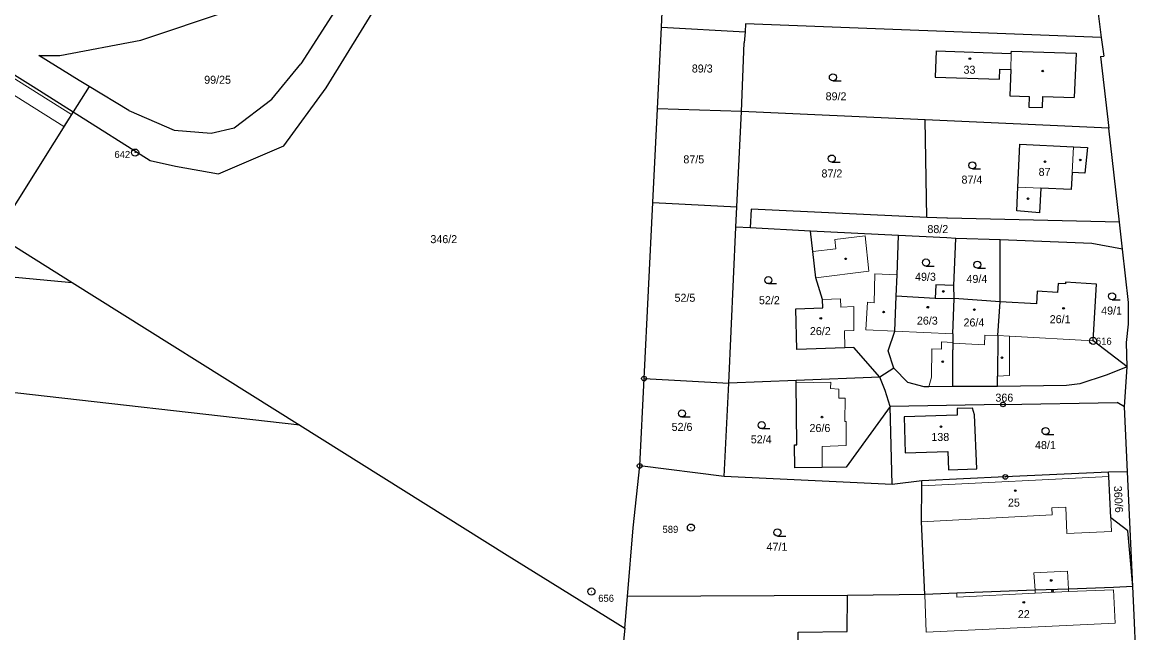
# Model space of a CAD drawing. Extents: x -645290 to -643454, y -1064771 to -1062356.
# Drawn here: x -644815.8 to -644579.3, y -1063657.6 to -1063528 of the extents above; entities that cross this region are included whole.
import ezdxf
from ezdxf.enums import TextEntityAlignment as Align

# ---------------------------------------------------------------- set-up
doc = ezdxf.new("R2010")
doc.units = 0
doc.header["$LTSCALE"] = 0.68
for name, color, linetype, lineweight in [('1', 7, 'Continuous', 25), ('13', 7, 'Continuous', 13), ('3', 7, 'Continuous', 25), ('4', 7, 'Continuous', 13), ('5', 7, 'Continuous', 25), ('8', 7, 'Continuous', 25)]:
    doc.layers.add(name, color=color, linetype=linetype, lineweight=lineweight)
doc.layers.add('2', color=7, linetype='Continuous')

msp = doc.modelspace()

# ---------------------------------------------------------------- linework, layer by layer
at = {"layer": '1'}
for p, q in [((-644680.03, -1063529.01), (-644678.93, -1063506.84)), ((-644589.39, -1063509.99), (-644586.6, -1063531.21)), ((-644743.97, -1063517.12), (-644756.66, -1063536.79)), ((-644751.27, -1063541.95), (-644735.12, -1063515.68)), ((-644790.62, -1063531.79), (-644771.77, -1063525.53)), ((-644680.89, -1063546.4), (-644680.03, -1063529.01)), ((-644680.03, -1063529.01), (-644662.28, -1063530.06)), ((-644662.16, -1063528.35), (-644662.28, -1063530.06)), ((-644586.6, -1063531.21), (-644662.16, -1063528.35)), ((-644662.28, -1063530.06), (-644662.43, -1063532.35)), ((-644586.6, -1063531.21), (-644586.08, -1063535.17)), ((-644807.8, -1063535.04), (-644790.62, -1063531.79)), ((-644663.05, -1063546.91), (-644662.43, -1063532.35)), ((-644824.28, -1063534.96), (-644813.5, -1063541.61)), ((-644803.7, -1063540.34), (-644812.29, -1063535.02)), ((-644812.29, -1063535.02), (-644807.8, -1063535.04)), ((-644621.67, -1063534.04), (-644621.87, -1063539.63)), ((-644621.67, -1063534.04), (-644605.72, -1063534.61)), ((-644605.72, -1063534.61), (-644605.71, -1063534.15)), ((-644605.71, -1063534.15), (-644591.95, -1063534.59)), ((-644591.95, -1063534.59), (-644592.37, -1063543.94)), ((-644586.76, -1063535.29), (-644586.08, -1063535.17)), ((-644586.76, -1063535.29), (-644585, -1063550.46)), ((-644762.81, -1063544.34), (-644756.66, -1063536.79)), ((-644608.24, -1063540.05), (-644608.17, -1063537.95)), ((-644608.17, -1063537.95), (-644605.83, -1063538.02)), ((-644605.83, -1063538.02), (-644606.01, -1063543.63)), ((-644801.59, -1063541.62), (-644803.7, -1063540.34)), ((-644621.87, -1063539.63), (-644608.24, -1063540.05)), ((-644813.5, -1063541.61), (-644804.99, -1063547)), ((-644801.59, -1063541.62), (-644804.99, -1063547)), ((-644793.15, -1063546.73), (-644801.59, -1063541.62)), ((-644760.23, -1063554.23), (-644751.27, -1063541.95)), ((-644770.83, -1063550.4), (-644762.81, -1063544.34)), ((-644606.01, -1063543.63), (-644601.9, -1063543.75)), ((-644601.9, -1063543.75), (-644601.97, -1063545.99)), ((-644599.09, -1063546.08), (-644599.02, -1063543.73)), ((-644599.02, -1063543.73), (-644592.37, -1063543.94)), ((-644804.99, -1063547), (-644820.87, -1063572.2)), ((-644804.99, -1063547), (-644788.64, -1063557.36)), ((-644793.15, -1063546.73), (-644783.51, -1063550.89)), ((-644681.88, -1063566.23), (-644680.89, -1063546.4)), ((-644663.05, -1063546.91), (-644680.89, -1063546.4)), ((-644664.01, -1063567.2), (-644663.05, -1063546.91)), ((-644624, -1063548.69), (-644663.05, -1063546.91)), ((-644601.97, -1063545.99), (-644599.09, -1063546.08)), ((-644775.65, -1063551.57), (-644770.83, -1063550.4)), ((-644585, -1063550.46), (-644624, -1063548.69)), ((-644623.68, -1063569.41), (-644624, -1063548.69)), ((-644582.74, -1063570.45), (-644585, -1063550.46)), ((-644783.51, -1063550.89), (-644775.65, -1063551.57)), ((-644774.12, -1063560.19), (-644760.23, -1063554.23)), ((-644604.32, -1063562.98), (-644603.9, -1063553.89)), ((-644603.9, -1063553.89), (-644592.51, -1063554.41)), ((-644592.51, -1063554.41), (-644589.57, -1063554.58)), ((-644589.57, -1063554.58), (-644590.07, -1063560.04)), ((-644788.64, -1063557.36), (-644783.26, -1063558.56)), ((-644783.26, -1063558.56), (-644774.12, -1063560.19)), ((-644592.81, -1063559.88), (-644593.01, -1063563.53)), ((-644590.07, -1063560.04), (-644592.81, -1063559.88)), ((-644604.57, -1063568.05), (-644604.32, -1063562.98)), ((-644599.45, -1063563.22), (-644599.71, -1063568.44)), ((-644593.01, -1063563.53), (-644599.45, -1063563.22)), ((-644683.74, -1063603.62), (-644681.88, -1063566.23)), ((-644681.88, -1063566.23), (-644664.01, -1063567.2)), ((-644664.22, -1063571.49), (-644664.01, -1063567.2)), ((-644661.01, -1063567.65), (-644661.22, -1063571.65)), ((-644623.68, -1063569.41), (-644661.01, -1063567.65)), ((-644619.43, -1063569.61), (-644623.68, -1063569.41)), ((-644599.71, -1063568.44), (-644604.57, -1063568.05)), ((-644665.72, -1063604.57), (-644664.22, -1063571.49)), ((-644661.22, -1063571.65), (-644664.22, -1063571.49)), ((-644648.38, -1063572.31), (-644661.22, -1063571.65)), ((-644619.25, -1063569.58), (-644619.43, -1063569.61)), ((-644582.74, -1063570.45), (-644619.25, -1063569.58)), ((-644582.11, -1063576.15), (-644582.74, -1063570.45)), ((-644821.41, -1063573.06), (-644805.19, -1063583.23)), ((-644629.69, -1063573.28), (-644648.38, -1063572.31)), ((-644647.89, -1063576.65), (-644648.38, -1063572.31)), ((-644630, -1063581.58), (-644629.69, -1063573.28)), ((-644619.43, -1063573.76), (-644629.69, -1063573.28)), ((-644617.5, -1063573.87), (-644619.43, -1063573.76)), ((-644617.95, -1063583.85), (-644617.5, -1063573.87)), ((-644608.07, -1063587.37), (-644608.06, -1063574.16)), ((-644582.11, -1063576.15), (-644588.61, -1063574.96)), ((-644580.8, -1063587.49), (-644582.11, -1063576.15)), ((-644647.26, -1063582.21), (-644647.89, -1063576.65)), ((-644828.49, -1063581.11), (-644805.19, -1063583.23)), ((-644805.19, -1063583.23), (-644756.87, -1063613.51)), ((-644645.82, -1063586.85), (-644647.26, -1063582.21)), ((-644630.16, -1063586.11), (-644630, -1063581.58)), ((-644595.76, -1063583.43), (-644595.88, -1063585.33)), ((-644594.22, -1063583.53), (-644595.76, -1063583.43)), ((-644594.2, -1063583.19), (-644594.22, -1063583.53)), ((-644587.59, -1063583.61), (-644594.2, -1063583.19)), ((-644588.35, -1063595.61), (-644587.59, -1063583.61)), ((-644621.76, -1063583.7), (-644621.86, -1063586.66)), ((-644617.95, -1063583.85), (-644621.76, -1063583.7)), ((-644617.84, -1063586.63), (-644617.95, -1063583.85)), ((-644600.23, -1063585.05), (-644600.4, -1063587.75)), ((-644595.88, -1063585.33), (-644600.23, -1063585.05)), ((-644645.76, -1063588.61), (-644645.82, -1063586.85)), ((-644630.48, -1063593.59), (-644630.16, -1063586.11)), ((-644621.86, -1063586.66), (-644630.16, -1063586.11)), ((-644618.12, -1063594.1), (-644617.84, -1063586.63)), ((-644608.07, -1063587.37), (-644617.84, -1063586.63)), ((-644608.6, -1063594.51), (-644608.07, -1063587.37)), ((-644600.4, -1063587.75), (-644608.07, -1063587.37)), ((-644580.8, -1063592.09), (-644580.8, -1063587.49)), ((-644651.51, -1063588.8), (-644645.76, -1063588.61)), ((-644651.31, -1063597.43), (-644651.51, -1063588.8)), ((-644581.22, -1063595.98), (-644580.8, -1063592.09)), ((-644631.85, -1063597.75), (-644630.48, -1063593.59)), ((-644618.12, -1063594.1), (-644618.13, -1063595.94)), ((-644608.6, -1063594.51), (-644608.66, -1063603.13)), ((-644641.06, -1063597.13), (-644651.31, -1063597.43)), ((-644639.14, -1063597.02), (-644641.06, -1063597.13)), ((-644633.66, -1063603.35), (-644639.14, -1063597.02)), ((-644630.67, -1063601.4), (-644631.85, -1063597.75)), ((-644618.15, -1063602.39), (-644618.14, -1063597.51)), ((-644618.13, -1063596.11), (-644618.14, -1063597.51)), ((-644618.13, -1063595.94), (-644618.13, -1063596.11)), ((-644581.09, -1063601.16), (-644588.35, -1063595.61)), ((-644581.09, -1063601.16), (-644581.22, -1063595.98)), ((-644630.67, -1063601.4), (-644633.66, -1063603.35)), ((-644627.72, -1063604.46), (-644630.67, -1063601.4)), ((-644618.16, -1063605.34), (-644618.15, -1063602.39)), ((-644581.09, -1063601.16), (-644585.6, -1063602.92)), ((-644581.67, -1063609.59), (-644581.09, -1063601.16)), ((-644684.66, -1063622.15), (-644683.74, -1063603.62)), ((-644683.74, -1063603.62), (-644665.72, -1063604.57)), ((-644666.68, -1063624.43), (-644665.72, -1063604.57)), ((-644651.42, -1063604.02), (-644665.72, -1063604.57)), ((-644633.66, -1063603.35), (-644651.42, -1063604.02)), ((-644651.41, -1063604.52), (-644651.42, -1063604.02)), ((-644651.25, -1063617.72), (-644651.41, -1063604.52)), ((-644632.51, -1063606.18), (-644633.66, -1063603.35)), ((-644624.26, -1063605.37), (-644627.72, -1063604.46)), ((-644608.68, -1063605.34), (-644608.66, -1063603.13)), ((-644591.19, -1063604.72), (-644593.97, -1063605.07)), ((-644585.6, -1063602.92), (-644591.19, -1063604.72)), ((-644631.44, -1063609.52), (-644632.51, -1063606.18)), ((-644623.21, -1063605.36), (-644624.26, -1063605.37)), ((-644618.16, -1063605.34), (-644623.21, -1063605.36)), ((-644608.68, -1063605.34), (-644618.16, -1063605.34)), ((-644593.97, -1063605.07), (-644608.68, -1063605.34)), ((-644631.44, -1063609.52), (-644640.78, -1063622.46)), ((-644607.5, -1063609.11), (-644631.44, -1063609.52)), ((-644631.03, -1063626.13), (-644631.44, -1063609.52)), ((-644607.5, -1063609.11), (-644583.22, -1063608.69)), ((-644581.67, -1063609.59), (-644583.22, -1063608.69)), ((-644581.02, -1063623.43), (-644581.67, -1063609.59)), ((-644617.19, -1063611.4), (-644628.49, -1063611.77)), ((-644628.49, -1063611.77), (-644628.24, -1063619.4)), ((-644617.23, -1063609.97), (-644617.19, -1063611.4)), ((-644613.06, -1063622.75), (-644613.53, -1063611.29)), ((-644756.87, -1063613.51), (-644712.83, -1063641.1)), ((-644651.79, -1063617.72), (-644651.25, -1063617.72)), ((-644651.73, -1063622.6), (-644651.79, -1063617.72)), ((-644628.24, -1063619.4), (-644619.22, -1063619.11)), ((-644619.22, -1063619.11), (-644619.09, -1063623)), ((-644686.06, -1063635.31), (-644684.66, -1063622.15)), ((-644666.68, -1063624.43), (-644684.66, -1063622.15)), ((-644645.92, -1063622.53), (-644651.73, -1063622.6)), ((-644640.78, -1063622.46), (-644645.92, -1063622.53)), ((-644619.09, -1063623), (-644613.06, -1063622.75)), ((-644585.06, -1063623.52), (-644606.99, -1063624.5)), ((-644581.02, -1063623.43), (-644585.06, -1063623.52)), ((-644579.89, -1063647.73), (-644581.02, -1063623.43)), ((-644631.03, -1063626.13), (-644666.68, -1063624.43)), ((-644624.76, -1063625.3), (-644631.03, -1063626.13)), ((-644606.99, -1063624.5), (-644624.76, -1063625.3)), ((-644624.76, -1063626.41), (-644624.76, -1063625.3)), ((-644624.77, -1063634.01), (-644624.76, -1063626.41)), ((-644687.26, -1063649.86), (-644686.06, -1063635.31)), ((-644624.1, -1063649.43), (-644624.77, -1063634.01)), ((-644712.83, -1063641.1), (-644687.82, -1063656.63)), ((-644687.82, -1063656.63), (-644687.26, -1063649.86)), ((-644640.52, -1063649.67), (-644687.26, -1063649.86)), ((-644640.58, -1063657.34), (-644640.52, -1063649.67)), ((-644624.1, -1063649.43), (-644640.52, -1063649.67)), ((-644617.31, -1063649.18), (-644624.1, -1063649.43)), ((-644600.67, -1063648.56), (-644617.31, -1063649.18)), ((-644593.57, -1063648.3), (-644600.67, -1063648.56)), ((-644583.98, -1063647.94), (-644593.57, -1063648.3)), ((-644579.89, -1063647.73), (-644583.98, -1063647.94)), ((-644579.62, -1063653.84), (-644579.89, -1063647.73)), ((-644579.29, -1063662.07), (-644579.62, -1063653.84)), ((-644687.82, -1063656.63), (-644689.27, -1063671.65)), ((-644651, -1063657.42), (-644640.58, -1063657.34)), ((-644650.67, -1063676.54), (-644651, -1063657.42))]:
    msp.add_line(p, q, dxfattribs=at)
for points in [[(-644588.61, -1063574.96), (-644608.06, -1063574.16), (-644617.5, -1063573.87)], [(-644756.87, -1063613.51), (-644820.57, -1063606.3), (-644900.64, -1063595.8)], [(-644613.53, -1063611.29), (-644613.99, -1063609.92), (-644617.23, -1063609.97)], [(-644579.89, -1063647.73), (-644580.94, -1063635.96), (-644584.58, -1063633.2), (-644585, -1063624.38), (-644585.06, -1063623.52)]]:
    msp.add_lwpolyline(points, dxfattribs=at)
at = {"layer": '13'}
msp.add_lwpolyline([(-644806.97, -1063550.15), (-644805.36, -1063547.59), (-644932.86, -1063467.39), (-645046.68, -1063395.8), (-645043.31, -1063390.69), (-645044.02, -1063386.31), (-645049.24, -1063394.23), (-645112.56, -1063356.35), (-645112.31, -1063359.17), (-645112.23, -1063360.04), (-645049.56, -1063397.54), (-644934.07, -1063470.19)], close=True, dxfattribs=at)
at = {"layer": '3'}
for p, q in [((-644643.613, -1063540.43), (-644641.863, -1063540.43)), ((-644643.853, -1063557.68), (-644642.103, -1063557.68)), ((-644613.983, -1063559.12), (-644612.233, -1063559.12)), ((-644623.843, -1063579.74), (-644622.093, -1063579.74)), ((-644612.923, -1063580.2), (-644611.173, -1063580.2)), ((-644657.323, -1063583.47), (-644655.573, -1063583.47)), ((-644584.313, -1063586.91), (-644582.563, -1063586.91)), ((-644675.683, -1063611.78), (-644673.933, -1063611.78)), ((-644658.743, -1063614.25), (-644656.993, -1063614.25)), ((-644598.443, -1063615.53), (-644596.693, -1063615.53)), ((-644655.393, -1063637.04), (-644653.643, -1063637.04))]:
    msp.add_line(p, q, dxfattribs=at)
for centre in [(-644643.6129, -1063539.6798), (-644643.8529, -1063556.9298), (-644613.9829, -1063558.3698), (-644623.8429, -1063578.9898), (-644612.9229, -1063579.4498), (-644657.3229, -1063582.7198), (-644584.3129, -1063586.1598), (-644675.6829, -1063611.0298), (-644658.7429, -1063613.4998), (-644598.4429, -1063614.7798), (-644655.3929, -1063636.2898)]:
    msp.add_circle(centre, 0.75, dxfattribs=at)
at = {"layer": '4'}
for p, q in [((-644605.72, -1063534.61), (-644605.83, -1063538.02)), ((-644592.81, -1063559.88), (-644592.51, -1063554.41)), ((-644604.32, -1063562.98), (-644599.45, -1063563.22)), ((-644636.74, -1063573.34), (-644643.19, -1063574.09)), ((-644643.19, -1063574.09), (-644642.97, -1063576.1)), ((-644635.96, -1063580.85), (-644636.74, -1063573.34)), ((-644642.97, -1063576.1), (-644647.89, -1063576.65)), ((-644647.26, -1063582.21), (-644635.96, -1063580.85)), ((-644634.72, -1063581.37), (-644634.88, -1063587.53)), ((-644630, -1063581.58), (-644634.72, -1063581.37)), ((-644641.97, -1063586.73), (-644645.82, -1063586.85)), ((-644641.91, -1063588.45), (-644641.97, -1063586.73)), ((-644639.18, -1063588.36), (-644641.91, -1063588.45)), ((-644639.14, -1063593.4), (-644639.18, -1063588.36)), ((-644636.25, -1063587.44), (-644636.61, -1063593.25)), ((-644634.88, -1063587.53), (-644636.25, -1063587.44)), ((-644617.84, -1063586.63), (-644621.86, -1063586.66)), ((-644639.14, -1063593.4), (-644641.14, -1063593.48)), ((-644641.14, -1063593.48), (-644641.06, -1063597.13)), ((-644636.61, -1063593.25), (-644630.48, -1063593.59)), ((-644618.12, -1063594.1), (-644630.48, -1063593.59)), ((-644611.32, -1063594.39), (-644611.43, -1063596.49)), ((-644611.32, -1063594.39), (-644608.6, -1063594.51)), ((-644606.12, -1063594.65), (-644606.08, -1063602.96)), ((-644611.43, -1063596.49), (-644618.13, -1063596.11)), ((-644651.41, -1063604.52), (-644644.04, -1063604.38)), ((-644644.04, -1063604.38), (-644644.11, -1063605.76)), ((-644606.08, -1063602.96), (-644608.66, -1063603.13)), ((-644644.11, -1063605.76), (-644642.38, -1063605.85)), ((-644642.38, -1063605.85), (-644642.35, -1063607.77)), ((-644642.35, -1063607.77), (-644641.01, -1063607.75)), ((-644641.01, -1063607.75), (-644641.06, -1063612.74)), ((-644641.06, -1063612.74), (-644640.81, -1063612.74)), ((-644640.81, -1063612.74), (-644640.79, -1063617.86)), ((-644645.88, -1063618.07), (-644645.92, -1063622.53)), ((-644640.79, -1063617.86), (-644645.88, -1063618.07)), ((-644585, -1063624.38), (-644624.76, -1063626.41)), ((-644594.14, -1063630.94), (-644597.14, -1063631.06)), ((-644593.9, -1063636.52), (-644594.14, -1063630.94)), ((-644597.06, -1063632.56), (-644624.77, -1063634.01)), ((-644597.14, -1063631.06), (-644597.06, -1063632.56)), ((-644584.58, -1063633.2), (-644584.45, -1063636.11)), ((-644584.45, -1063636.11), (-644593.9, -1063636.52)), ((-644593.79, -1063644.51), (-644600.91, -1063644.83)), ((-644600.91, -1063644.83), (-644600.67, -1063648.56)), ((-644593.57, -1063648.3), (-644593.79, -1063644.51)), ((-644623.82, -1063657.43), (-644624.1, -1063649.43)), ((-644617.31, -1063649.18), (-644617.28, -1063650.02)), ((-644617.28, -1063650.02), (-644600.63, -1063649.19)), ((-644600.67, -1063648.56), (-644600.63, -1063649.19)), ((-644600.63, -1063649.19), (-644593.54, -1063648.84)), ((-644593.54, -1063648.84), (-644593.57, -1063648.3)), ((-644584.01, -1063648.44), (-644593.54, -1063648.84)), ((-644584.01, -1063648.44), (-644583.64, -1063655.51)), ((-644583.64, -1063655.51), (-644623.82, -1063657.43))]:
    msp.add_line(p, q, dxfattribs=at)
for points in [[(-644588.35, -1063595.61), (-644606.12, -1063594.65), (-644608.6, -1063594.51)], [(-644618.13, -1063595.94), (-644620.52, -1063595.86), (-644620.58, -1063597.38), (-644622.6, -1063597.31), (-644622.66, -1063603.34), (-644623.21, -1063605.36)]]:
    msp.add_lwpolyline(points, dxfattribs=at)
at = {"layer": '5'}
for centre in [(-644614.5168, -1063535.7292), (-644599.0468, -1063538.3592), (-644598.5568, -1063557.5892), (-644591.0668, -1063557.2192), (-644602.1568, -1063565.4492), (-644640.9168, -1063578.2092), (-644620.1668, -1063585.1392), (-644623.4668, -1063588.4792), (-644646.1968, -1063590.8292), (-644632.8468, -1063589.4992), (-644613.5668, -1063588.9992), (-644594.6268, -1063588.7092), (-644620.2968, -1063600.0392), (-644607.7068, -1063599.1992), (-644645.9168, -1063611.7992), (-644620.6668, -1063613.8392), (-644604.8668, -1063627.3992), (-644597.2468, -1063646.4792), (-644596.9668, -1063648.7292), (-644603.0668, -1063651.1292)]:
    msp.add_circle(centre, 0.175, dxfattribs=at)
at = {"layer": '8'}
for centre, radius in [((-644791.83, -1063555.6498), 0.75), ((-644791.83, -1063555.6498), 0.03), ((-644588.35, -1063595.6098), 0.75), ((-644588.35, -1063595.6098), 0.03), ((-644683.74, -1063603.6199), 0.5), ((-644683.74, -1063603.6199), 0.0303), ((-644607.5, -1063609.1099), 0.5), ((-644607.5, -1063609.1099), 0.0303), ((-644684.66, -1063622.1499), 0.5), ((-644684.66, -1063622.1499), 0.0303), ((-644606.99, -1063624.4999), 0.5), ((-644606.99, -1063624.4999), 0.0303), ((-644673.78, -1063635.2498), 0.75), ((-644673.78, -1063635.2498), 0.03), ((-644694.91, -1063648.8198), 0.75), ((-644694.91, -1063648.8198), 0.03)]:
    msp.add_circle(centre, radius, dxfattribs=at)

# ---------------------------------------------------------------- texts
at = {"layer": '2'}
for s, p in [('89/3', (-644673.58, -1063538.665)), ('87/5', (-644675.38, -1063557.945)), ('52/5', (-644677.26, -1063587.324)), ('52/6', (-644677.87, -1063614.735))]:
    msp.add_text(s, height=1.7, dxfattribs=at).set_placement(p)
for s, p in [('33', (-644614.609, -1063538.925)), ('99/25', (-644774.32, -1063541.054)), ('89/2', (-644642.949, -1063544.564)), ('87/2', (-644643.829, -1063560.945)), ('87', (-644598.649, -1063560.615)), ('87/4', (-644614.089, -1063562.245)), ('88/2', (-644621.329, -1063572.745)), ('346/2', (-644726.27, -1063574.885)), ('49/3', (-644623.949, -1063582.865)), ('49/4', (-644613.029, -1063583.324)), ('52/2', (-644657.109, -1063587.844)), ('49/1', (-644584.419, -1063590.035)), ('26/3', (-644623.559, -1063592.175)), ('26/1', (-644595.349, -1063591.875)), ('26/2', (-644646.289, -1063594.395)), ('26/4', (-644613.659, -1063592.564)), ('366', (-644607.199, -1063608.525)), ('26/6', (-644646.369, -1063614.975)), ('52/4', (-644658.849, -1063617.375)), ('138', (-644620.799, -1063616.865)), ('48/1', (-644598.469, -1063618.584)), ('25', (-644605.169, -1063630.804)), ('47/1', (-644655.499, -1063640.165)), ('22', (-644603.069, -1063654.475))]:
    msp.add_text(s, height=1.7, dxfattribs=at).set_placement(p, align=Align.CENTER)
msp.add_text('360/6', height=1.7, rotation=273, dxfattribs=at).set_placement((-644583.8024, -1063629.2845), align=Align.CENTER)
at = {"layer": '8'}
for s, p in [('642', (-644796.23, -1063556.804)), ('656', (-644693.46, -1063651.004))]:
    msp.add_text(s, height=1.5, dxfattribs=at).set_placement(p)
for s, p in [('616', (-644584.399, -1063596.447)), ('589', (-644676.459, -1063636.377))]:
    msp.add_text(s, height=1.5, dxfattribs=at).set_placement(p, align=Align.RIGHT)

doc.saveas('drawing.dxf')
